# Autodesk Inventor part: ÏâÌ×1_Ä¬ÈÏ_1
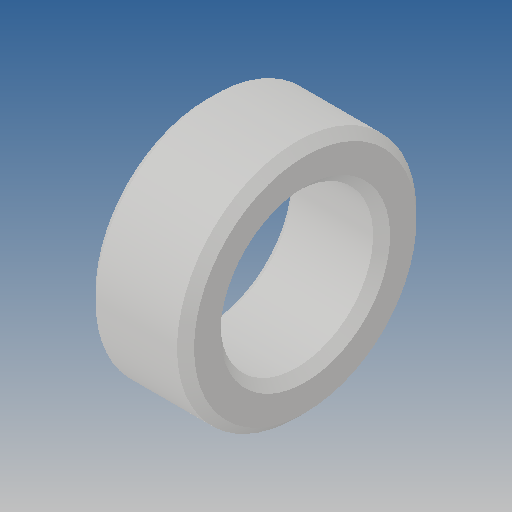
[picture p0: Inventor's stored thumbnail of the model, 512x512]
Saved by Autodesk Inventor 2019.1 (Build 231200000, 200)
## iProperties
Created: 2012-10
Part Number: ÏâÌ×1_Ä¬ÈÏ_1
Material: Ogólny
Document SubType Name: Modeling
Designer: CADENGINEERING4
Density: 1 g/cm^3
Appearance: Domyślna
Author: CADENGINEERING4
Revision Number: ÈÎºÎ
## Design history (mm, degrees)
feature "NONE"
node "Bryła1"
